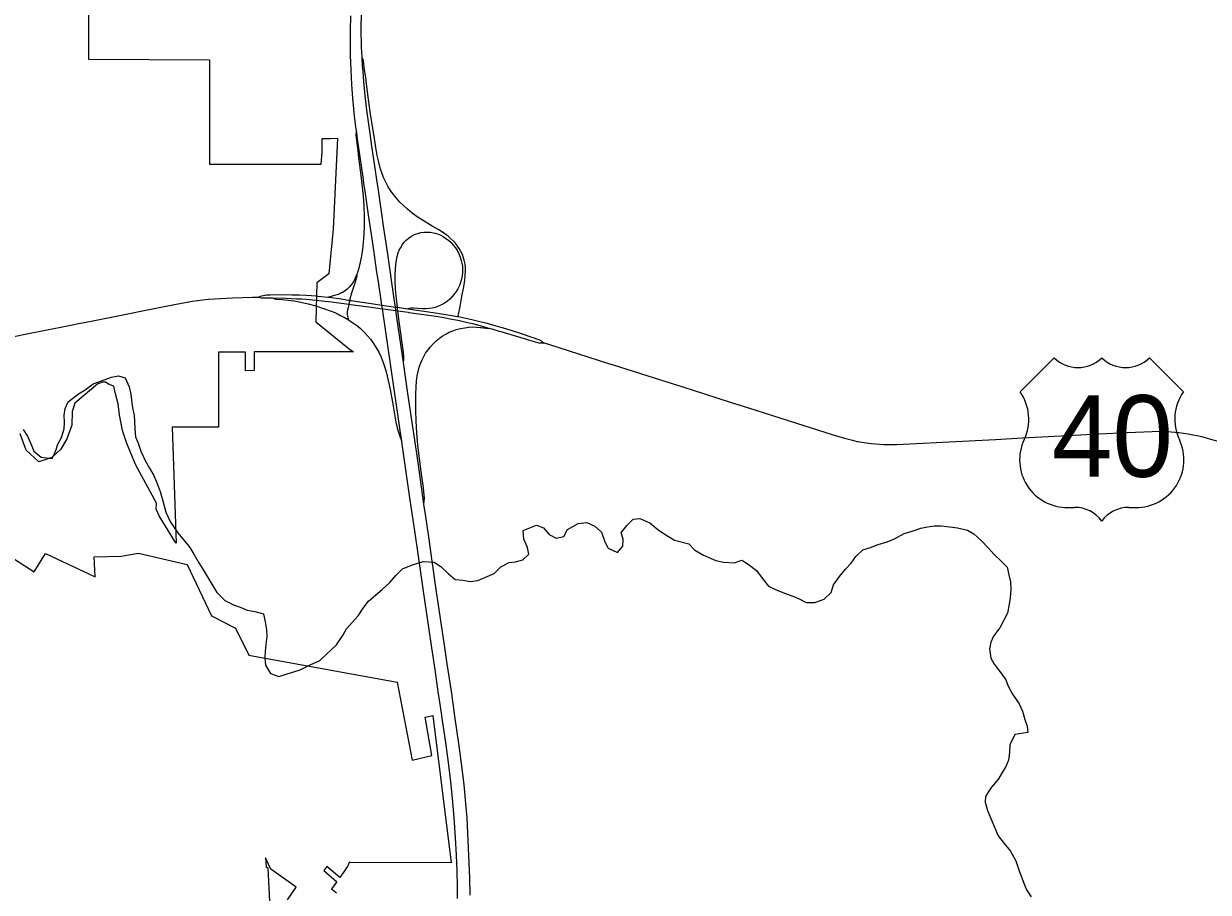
# Model space of a CAD drawing. Extents: x -29.6 to 34, y 0 to 22.
# Drawn here: x 4.78 to 7.023, y 15.149 to 16.793 of the extents above; entities that cross this region are included whole.
import ezdxf

# ---------------------------------------------------------------- set-up
doc = ezdxf.new("R2010")
doc.units = 0
for name, color, linetype in [('GM_X_Corporation', 7, 'Continuous'), ('GM_X_Interchange_Ramps', 7, 'Continuous'), ('GM_X_Interstate_Route', 7, 'Continuous'), ('GM_X_Minor_River', 7, 'Continuous'), ('GM_X_US_Route', 7, 'Continuous'), ('GM_X_US_Shield', 7, 'Continuous')]:
    doc.layers.add(name, color=color, linetype=linetype)

msp = doc.modelspace()

# ---------------------------------------------------------------- linework, layer by layer
at = {"layer": 'GM_X_Corporation'}
for points in [[(4.9028, 16.8101), (4.9028, 16.7263), (5.132, 16.7248), (5.132, 16.5273), (5.3437, 16.5274), (5.345, 16.5498), (5.3452, 16.5763), (5.3605, 16.5761), (5.3741, 16.5767), (5.3661, 16.4042), (5.3581, 16.3201), (5.3349, 16.3026), (5.3331, 16.2292), (5.3961, 16.178), (5.4045, 16.1724), (5.3388, 16.1724), (5.2167, 16.1724), (5.2167, 16.1371), (5.2001, 16.1361), (5.2001, 16.1716), (5.149, 16.1716), (5.149, 16.0297), (5.061, 16.0296), (5.0687, 15.8101), (5.0658, 15.8145), (5.0369, 15.8619), (5.0312, 15.874), (5.0318, 15.8857), (4.9919, 15.9586), (4.9821, 15.9835), (4.9751, 16.0008), (4.967, 16.0233), (4.9618, 16.0528), (4.959, 16.0736), (4.9543, 16.0926), (4.9509, 16.1071), (4.9422, 16.1106), (4.9353, 16.1146), (4.9295, 16.1146), (4.9203, 16.1117), (4.8771, 16.0751), (4.8717, 16.0591), (4.8711, 16.0331), (4.862, 16.0072), (4.8508, 15.9878), (4.8336, 15.9721), (4.809, 15.9638), (4.7852, 15.9862), (4.7733, 16.0172)], [(4.7451, 15.7911), (4.8002, 15.7559), (4.8217, 15.7904), (4.9154, 15.7459), (4.9137, 15.7841), (4.9645, 15.7851), (4.9978, 15.791), (5.0895, 15.7694), (5.1357, 15.6726), (5.1812, 15.649), (5.2066, 15.5978), (5.4873, 15.5465), (5.5157, 15.399), (5.5531, 15.4077), (5.5404, 15.4802), (5.5545, 15.4835), (5.5896, 15.2044), (5.3981, 15.2052), (5.3971, 15.2062), (5.3954, 15.2018), (5.3946, 15.2), (5.3936, 15.1982), (5.3929, 15.197), (5.3866, 15.1876), (5.3786, 15.1767), (5.354, 15.1979), (5.3487, 15.1899), (5.3729, 15.1688), (5.3632, 15.1551), (5.3722, 15.1481)], [(5.2797, 15.1344), (5.2959, 15.1588), (5.2482, 15.1927), (5.2382, 15.2139), (5.239, 15.1973), (5.2424, 15.1949), (5.2462, 15.1189)]]:
    msp.add_lwpolyline(points, dxfattribs=at)
at = {"layer": 'GM_X_Interchange_Ramps'}
for points in [[(5.6026, 16.2391), (5.6033, 16.2426), (5.6063, 16.2581), (5.6099, 16.2769), (5.6135, 16.2955), (5.6154, 16.3077), (5.6162, 16.3165), (5.6167, 16.3251), (5.6164, 16.3324), (5.6157, 16.3382), (5.6142, 16.346), (5.613, 16.3502), (5.6107, 16.3564), (5.608, 16.3623), (5.6048, 16.3681), (5.6024, 16.3717), (5.5975, 16.378), (5.5941, 16.3818), (5.5872, 16.3883), (5.5838, 16.3911), (5.5749, 16.3974), (5.5663, 16.4029), (5.5537, 16.4103), (5.5351, 16.4216), (5.5271, 16.4268), (5.5159, 16.4349), (5.5068, 16.4421), (5.4992, 16.449), (5.4925, 16.4556), (5.4857, 16.4632), (5.4799, 16.4707), (5.4748, 16.4778), (5.4699, 16.4859), (5.4657, 16.4936), (5.4617, 16.5021), (5.4575, 16.513), (5.4559, 16.5178), (5.4523, 16.5312), (5.4497, 16.544), (5.447, 16.5591), (5.4444, 16.5764), (5.4371, 16.6224), (5.433, 16.6498), (5.4293, 16.6794), (5.4277, 16.6913), (5.4256, 16.7063), (5.4243, 16.7175), (5.4237, 16.7222), (5.4234, 16.7238), (5.4231, 16.7249), (5.4227, 16.7259), (5.4224, 16.7267), (5.4217, 16.7284), (5.4209, 16.7297)], [(5.4103, 16.5908), (5.4098, 16.5886), (5.4094, 16.5865), (5.4092, 16.585), (5.4092, 16.5824), (5.4134, 16.5472), (5.4135, 16.5454), (5.4192, 16.5011), (5.4212, 16.4837), (5.4228, 16.4671), (5.424, 16.4482), (5.4247, 16.4278), (5.4247, 16.4104), (5.4242, 16.3944), (5.423, 16.3791), (5.4216, 16.3668), (5.4198, 16.3539), (5.4175, 16.3417), (5.4148, 16.3304), (5.4117, 16.3207), (5.4111, 16.319), (5.4093, 16.3146), (5.4065, 16.3086), (5.404, 16.3043), (5.4002, 16.2989), (5.3969, 16.2951), (5.3927, 16.2911), (5.3886, 16.2879), (5.3837, 16.2848), (5.3818, 16.2837), (5.38, 16.2829), (5.3778, 16.2818), (5.3754, 16.2809), (5.3731, 16.2801), (5.3601, 16.2763), (5.3577, 16.2756)], [(5.499, 16.152), (5.4998, 16.1569), (5.5001, 16.16), (5.5001, 16.1627), (5.4994, 16.1715), (5.4905, 16.2343), (5.4884, 16.2498), (5.4881, 16.2523), (5.4876, 16.2565), (5.4859, 16.2726), (5.4843, 16.2914), (5.4836, 16.3067), (5.4835, 16.3184), (5.4838, 16.3278), (5.4845, 16.3373), (5.4857, 16.346), (5.4871, 16.3524), (5.4891, 16.3593), (5.4913, 16.3648), (5.4939, 16.37), (5.4974, 16.3755), (5.5006, 16.3795), (5.5046, 16.3837), (5.5079, 16.3866), (5.5126, 16.39), (5.5164, 16.3922), (5.5216, 16.3947), (5.5264, 16.3963), (5.5321, 16.3978), (5.5379, 16.3986), (5.543, 16.3989), (5.5488, 16.3987), (5.5531, 16.3981), (5.5595, 16.3967), (5.5637, 16.3954), (5.5697, 16.3928), (5.5742, 16.3905), (5.5797, 16.3869), (5.5843, 16.3833), (5.5892, 16.3789), (5.5936, 16.3741), (5.5976, 16.3689), (5.6012, 16.3634), (5.6042, 16.3575), (5.6067, 16.3515), (5.6087, 16.3452), (5.6098, 16.3403), (5.6107, 16.3338), (5.611, 16.3287), (5.6109, 16.3221), (5.6103, 16.3163), (5.6091, 16.3099), (5.6073, 16.3036), (5.605, 16.2975), (5.6021, 16.2916), (5.5992, 16.2865), (5.5954, 16.2812), (5.5916, 16.2767), (5.587, 16.2721), (5.5825, 16.2684), (5.5771, 16.2646), (5.5714, 16.2614), (5.5655, 16.2586), (5.5593, 16.2564), (5.5537, 16.2549), (5.5479, 16.2539), (5.5414, 16.2534), (5.5356, 16.2534), (5.5179, 16.2546), (5.5136, 16.2546), (5.5101, 16.2543), (5.5075, 16.2536)], [(5.4111, 16.319), (5.4106, 16.3161), (5.41, 16.3127), (5.4086, 16.3072), (5.4083, 16.3058), (5.4044, 16.2943), (5.3993, 16.2793), (5.3987, 16.2765), (5.3979, 16.2724), (5.3974, 16.27), (5.3966, 16.2658), (5.3958, 16.2624)], [(5.2514, 16.2744), (5.2527, 16.2737), (5.2548, 16.2726), (5.2566, 16.2722), (5.2585, 16.2719), (5.2704, 16.2713), (5.2757, 16.2709), (5.2811, 16.2702), (5.2865, 16.2696), (5.292, 16.2688), (5.3049, 16.2664), (5.319, 16.2631), (5.3332, 16.259)], [(5.3958, 16.2624), (5.3943, 16.2554), (5.3934, 16.2517), (5.3926, 16.2488), (5.3923, 16.2459), (5.3925, 16.2429), (5.3931, 16.2404), (5.3941, 16.237), (5.3954, 16.2326)], [(5.3332, 16.259), (5.3481, 16.2542), (5.3623, 16.2491), (5.3692, 16.2464), (5.3756, 16.2434), (5.3785, 16.2419), (5.3876, 16.2372), (5.3954, 16.2326), (5.397, 16.2317), (5.4055, 16.2261), (5.4125, 16.2208), (5.418, 16.2162), (5.4249, 16.2096), (5.4313, 16.2027), (5.4368, 16.1959), (5.4423, 16.1882), (5.4478, 16.1796), (5.4524, 16.1714), (5.4569, 16.1622), (5.461, 16.1521), (5.4642, 16.1424), (5.4666, 16.134), (5.4705, 16.1177), (5.474, 16.1006), (5.4784, 16.077), (5.4847, 16.0393), (5.4874, 16.028), (5.4896, 16.0201), (5.4917, 16.0142), (5.4961, 16.0015)], [(5.538, 15.884), (5.5384, 15.8891), (5.5389, 15.8948), (5.5387, 15.9008), (5.5371, 15.9146), (5.5328, 15.9456), (5.5289, 15.9745), (5.5265, 15.9962), (5.5246, 16.0179), (5.5232, 16.0412), (5.5225, 16.0616), (5.5224, 16.0783), (5.5226, 16.0921), (5.5231, 16.106), (5.524, 16.1169), (5.5254, 16.127), (5.527, 16.1348), (5.5291, 16.1433), (5.5321, 16.1515), (5.5343, 16.1569), (5.5382, 16.1647), (5.5412, 16.1696), (5.5458, 16.1762), (5.5504, 16.1819), (5.5558, 16.1878), (5.5611, 16.1928), (5.5673, 16.1978), (5.5726, 16.2016), (5.5795, 16.2058), (5.586, 16.2091), (5.5927, 16.2119), (5.5996, 16.2142), (5.6073, 16.2163), (5.6152, 16.2179), (5.6231, 16.2189), (5.6304, 16.2192), (5.6377, 16.2191), (5.6442, 16.2185), (5.6466, 16.2181), (5.655, 16.2171), (5.6588, 16.2168), (5.6629, 16.2166)]]:
    msp.add_lwpolyline(points, dxfattribs=at)
at = {"layer": 'GM_X_Interstate_Route'}
for points in [[(5.6016, 15.1368), (5.6014, 15.1594), (5.6007, 15.1893), (5.5995, 15.2191), (5.5978, 15.2519), (5.5953, 15.2904), (5.5921, 15.3267), (5.5888, 15.3585), (5.5844, 15.3947), (5.5793, 15.4322), (5.573, 15.474), (5.5703, 15.4923), (5.5666, 15.5168), (5.5656, 15.5237), (5.5589, 15.5705), (5.553, 15.6116), (5.5368, 15.7233), (5.5276, 15.7852), (5.5205, 15.8335), (5.5121, 15.8911), (5.4961, 16.0015), (5.46, 16.249), (5.4594, 16.2537), (5.4584, 16.2607), (5.4558, 16.279), (5.454, 16.2912), (5.4524, 16.3003), (5.4484, 16.3275), (5.4438, 16.3603), (5.4398, 16.3859), (5.4339, 16.4272), (5.4265, 16.4762), (5.4244, 16.4908), (5.4229, 16.503), (5.4156, 16.5541), (5.413, 16.571), (5.4103, 16.5908), (5.4091, 16.5985), (5.4077, 16.608), (5.4065, 16.619), (5.4035, 16.6527), (5.4016, 16.6781), (5.4001, 16.7064), (5.3992, 16.7333), (5.3989, 16.7588), (5.399, 16.7806), (5.3998, 16.8082)], [(5.4854, 16.2469), (5.485, 16.2502), (5.484, 16.257), (5.4819, 16.2722), (5.479, 16.2903), (5.4765, 16.3077), (5.4739, 16.326), (5.4712, 16.3439), (5.4687, 16.3614), (5.4621, 16.4062), (5.4582, 16.4332), (5.4545, 16.4601), (5.4519, 16.478), (5.4486, 16.4981), (5.4464, 16.5153), (5.4395, 16.5618), (5.4359, 16.5856), (5.43, 16.6296), (5.4284, 16.6409), (5.4268, 16.6566), (5.424, 16.6847), (5.4233, 16.6926), (5.4226, 16.7036), (5.4219, 16.7132), (5.4209, 16.7297), (5.4209, 16.7306), (5.4198, 16.7482), (5.4193, 16.7851), (5.4195, 16.8135)], [(5.553, 15.7803), (5.5476, 15.8174), (5.5413, 15.8606), (5.538, 15.884), (5.5301, 15.9399), (5.5236, 15.9839), (5.5073, 16.0933), (5.499, 16.152), (5.4869, 16.237), (5.4854, 16.2469)], [(5.6252, 15.1435), (5.6247, 15.1755), (5.6204, 15.2752), (5.6197, 15.2897), (5.618, 15.31), (5.6138, 15.352), (5.6102, 15.3831), (5.6045, 15.4264), (5.5967, 15.4826), (5.5947, 15.4968), (5.5913, 15.5201), (5.5911, 15.5216), (5.5821, 15.5812), (5.5769, 15.6165), (5.5613, 15.7224), (5.5537, 15.7757), (5.553, 15.7803)]]:
    msp.add_lwpolyline(points, dxfattribs=at)
at = {"layer": 'GM_X_Minor_River'}
for points in [[(4.9118, 16.1114), (4.9277, 16.1172), (4.9462, 16.124), (4.9595, 16.1264), (4.9724, 16.1229), (4.98, 16.1056), (4.9828, 16.0923), (4.9846, 16.0804), (4.9865, 16.0662), (4.9893, 16.052), (4.9902, 16.04), (4.9908, 16.0258), (4.9922, 16.0111), (4.9967, 15.9992), (5.0017, 15.9841), (5.0102, 15.9664), (5.0183, 15.9518), (5.0263, 15.9377), (5.0331, 15.9231), (5.0385, 15.908), (5.0435, 15.8903), (5.0494, 15.8686), (5.0584, 15.8496), (5.0718, 15.8297), (5.0839, 15.8151), (5.0946, 15.8019), (5.1022, 15.7891), (5.112, 15.7727), (5.1214, 15.7577), (5.1291, 15.7448), (5.1362, 15.7325), (5.1461, 15.7166), (5.1608, 15.7011), (5.1772, 15.6928), (5.1901, 15.6889), (5.2034, 15.6828), (5.2181, 15.6802), (5.234, 15.6759), (5.2382, 15.6577), (5.24, 15.6458), (5.2405, 15.6329), (5.2389, 15.6182), (5.2376, 15.6053), (5.2368, 15.5925), (5.2378, 15.5791), (5.2477, 15.5632), (5.2632, 15.5571), (5.2773, 15.5621), (5.3034, 15.5703), (5.3228, 15.5793), (5.3409, 15.5875), (5.3537, 15.5995), (5.3726, 15.6174), (5.3853, 15.6366), (5.3915, 15.6478), (5.402, 15.6594), (5.4135, 15.6724), (5.4227, 15.6871), (5.4328, 15.7), (5.446, 15.7112), (5.4587, 15.7224), (5.4733, 15.7354), (5.4847, 15.7488), (5.4974, 15.7614), (5.5142, 15.7681), (5.5363, 15.775), (5.5576, 15.7738), (5.5701, 15.7655), (5.5839, 15.7522), (5.5968, 15.7412), (5.6123, 15.7396), (5.6252, 15.7374), (5.6402, 15.7393), (5.6707, 15.7524), (5.6834, 15.765), (5.6993, 15.7731), (5.7113, 15.7745), (5.725, 15.7786), (5.7364, 15.7889), (5.7341, 15.8018), (5.7269, 15.8177), (5.7259, 15.8341), (5.7511, 15.8441), (5.7644, 15.8388), (5.7752, 15.8265), (5.7885, 15.8195), (5.8026, 15.8222), (5.8096, 15.8356), (5.8299, 15.8469), (5.8463, 15.8492), (5.8614, 15.8418), (5.8739, 15.8308), (5.8802, 15.8122), (5.8869, 15.8007), (5.9043, 15.7924), (5.9148, 15.8044), (5.9152, 15.8173), (5.9111, 15.8293), (5.9221, 15.8435), (5.934, 15.8552), (5.9468, 15.8566)], [(4.7795, 16.0251), (4.7876, 16.0123), (4.7943, 15.9968), (4.7997, 15.984), (4.8135, 15.9725), (4.8343, 15.9705), (4.8409, 15.9852), (4.8448, 15.9972), (4.8518, 16.0101), (4.8566, 16.0266), (4.8574, 16.0381), (4.8568, 16.0523), (4.8585, 16.0648), (4.8642, 16.0777), (4.884, 16.0925), (4.8964, 16.1001), (4.9118, 16.1114)], [(5.9468, 15.8566), (5.9655, 15.8483), (5.981, 15.836), (5.9926, 15.8276), (6.0126, 15.8154), (6.0392, 15.8084), (6.0504, 15.7974), (6.0669, 15.7873), (6.0908, 15.7773), (6.105, 15.7738), (6.1259, 15.7727), (6.14, 15.7777), (6.152, 15.7698), (6.1676, 15.7583), (6.1783, 15.7437), (6.1904, 15.7283), (6.2037, 15.7222), (6.2206, 15.7152), (6.2366, 15.7095), (6.2481, 15.7043), (6.2614, 15.6977), (6.2783, 15.6974), (6.2955, 15.7038), (6.3092, 15.7163), (6.3135, 15.731), (6.3249, 15.747), (6.3359, 15.7604), (6.3469, 15.7721), (6.3556, 15.7846), (6.3688, 15.7971), (6.3834, 15.8016), (6.398, 15.8075), (6.4148, 15.8121), (6.4285, 15.8179), (6.447, 15.8283), (6.4643, 15.8333), (6.4784, 15.8383), (6.4912, 15.841), (6.5045, 15.8429), (6.5174, 15.8426), (6.5338, 15.8405), (6.5479, 15.8388), (6.567, 15.8345), (6.579, 15.8275), (6.5928, 15.8151), (6.6067, 15.8006), (6.6169, 15.7891), (6.6312, 15.7754), (6.6423, 15.7644), (6.6451, 15.7498), (6.6483, 15.7365), (6.6488, 15.7227), (6.6476, 15.7063), (6.6455, 15.6907), (6.6425, 15.6774), (6.6281, 15.6493), (6.6162, 15.6337), (6.6114, 15.6226), (6.6088, 15.6101), (6.6112, 15.5924), (6.6174, 15.5809), (6.6304, 15.5645), (6.6393, 15.5513), (6.6443, 15.5393), (6.6519, 15.5238), (6.6649, 15.5057), (6.6712, 15.4916), (6.6757, 15.476), (6.6798, 15.4632), (6.6812, 15.4512), (6.6564, 15.4475), (6.6473, 15.4279), (6.6465, 15.4132), (6.6448, 15.399), (6.6396, 15.387), (6.6325, 15.3758), (6.6255, 15.3634), (6.6106, 15.3455), (6.6014, 15.3303), (6.6002, 15.3192), (6.6047, 15.3037), (6.6101, 15.2918), (6.6182, 15.2723), (6.6249, 15.2559), (6.6366, 15.2413), (6.6486, 15.2268), (6.6585, 15.2086), (6.6643, 15.1914), (6.6725, 15.1692), (6.6788, 15.1537), (6.6873, 15.1405)]]:
    msp.add_lwpolyline(points, dxfattribs=at)
at = {"layer": 'GM_X_US_Route'}
for points in [[(4.7331, 16.1955), (4.7585, 16.2006), (4.786, 16.2061), (4.8634, 16.2216), (4.8839, 16.2256), (4.8913, 16.2271), (4.9141, 16.2317), (4.9491, 16.2387), (4.9805, 16.2449), (4.9986, 16.2485), (5.049, 16.2587), (5.079, 16.2646), (5.0897, 16.2664), (5.1, 16.2682), (5.1093, 16.2695), (5.1102, 16.2696), (5.1192, 16.2709), (5.1294, 16.2718), (5.1413, 16.2728), (5.1753, 16.2745), (5.2133, 16.2755), (5.2248, 16.2759)], [(5.2248, 16.2759), (5.2288, 16.2775), (5.2337, 16.279), (5.2399, 16.28), (5.2471, 16.2804), (5.2623, 16.2806), (5.2877, 16.2801), (5.3019, 16.2799), (5.3141, 16.2794), (5.3251, 16.2787), (5.3335, 16.2781)], [(5.2248, 16.2759), (5.23, 16.2747), (5.2349, 16.2742), (5.2514, 16.2744), (5.2776, 16.2737), (5.2969, 16.2728), (5.298, 16.2728)], [(5.298, 16.2728), (5.3062, 16.2724), (5.3147, 16.2717), (5.3333, 16.2698)], [(5.3333, 16.2698), (5.3627, 16.2668), (5.3958, 16.2624)], [(5.3335, 16.2781), (5.3378, 16.2777), (5.356, 16.2758), (5.3577, 16.2756), (5.3777, 16.273), (5.3951, 16.2703)], [(5.3951, 16.2703), (5.3974, 16.27), (5.3994, 16.2696), (5.4422, 16.2631), (5.4584, 16.2607), (5.484, 16.257), (5.4876, 16.2565), (5.4956, 16.2553), (5.5075, 16.2536), (5.5554, 16.2466), (5.5835, 16.2425), (5.6015, 16.2393)], [(5.3958, 16.2624), (5.4038, 16.2613), (5.4385, 16.2566)], [(5.4385, 16.2566), (5.4594, 16.2537), (5.4608, 16.2536), (5.485, 16.2502), (5.4884, 16.2498), (5.508, 16.2471)], [(5.508, 16.2471), (5.5092, 16.2469), (5.561, 16.2394), (5.5754, 16.237), (5.5905, 16.2343), (5.602, 16.232)], [(5.6015, 16.2393), (5.6026, 16.2391), (5.6057, 16.2385), (5.6285, 16.2335), (5.644, 16.2298), (5.6575, 16.2264), (5.6631, 16.2248)], [(5.602, 16.232), (5.6054, 16.2313), (5.6177, 16.2286), (5.6302, 16.2255), (5.6437, 16.2221), (5.6629, 16.2166)], [(5.6629, 16.2166), (5.6665, 16.2157), (5.6805, 16.2116), (5.6836, 16.2107), (5.728, 16.1975), (5.7532, 16.1899), (5.7555, 16.1893), (5.7578, 16.189), (5.7601, 16.1889), (5.7654, 16.1891)], [(5.6631, 16.2248), (5.6813, 16.2197), (5.6858, 16.2183), (5.7042, 16.2125), (5.7218, 16.2067), (5.7565, 16.1947), (5.7592, 16.1934), (5.7614, 16.192), (5.7654, 16.1891)], [(5.7654, 16.1891), (5.7874, 16.182), (5.7954, 16.1795)], [(5.7954, 16.1795), (5.8305, 16.1684), (5.8873, 16.1502), (5.8941, 16.148), (5.9478, 16.1312), (6.0456, 16.1), (6.1178, 16.077), (6.1524, 16.0659), (6.2572, 16.0327), (6.3127, 16.0149), (6.3343, 16.0084), (6.3491, 16.0046), (6.358, 16.0026), (6.3596, 16.0024), (6.3669, 16.0012), (6.3761, 15.9997), (6.3848, 15.9986), (6.3926, 15.9977), (6.4007, 15.9971), (6.4078, 15.9967), (6.4152, 15.9966), (6.4326, 15.9968), (6.4828, 15.9992), (6.5322, 16.0019), (6.62, 16.0063), (6.6704, 16.0092), (6.7809, 16.0149), (6.8158, 16.0168), (6.8696, 16.0197), (6.9168, 16.0214), (6.9323, 16.0217), (6.9422, 16.0214), (6.9527, 16.0208), (6.9602, 16.0201), (6.9659, 16.0196)], [(6.9659, 16.0196), (6.968, 16.0194), (6.9762, 16.0183), (6.9846, 16.0169), (6.9939, 16.0151), (7.0018, 16.0135), (7.0099, 16.0117), (7.0188, 16.0092), (7.027, 16.0069), (7.0363, 16.004), (7.0441, 16.0015), (7.0529, 15.9983), (7.0601, 15.9955), (7.0671, 15.9925), (7.0836, 15.9848), (7.0923, 15.9806), (7.1005, 15.9761), (7.1088, 15.9714), (7.1192, 15.9651)]]:
    msp.add_lwpolyline(points, dxfattribs=at)
at = {"layer": 'GM_X_US_Shield'}
for p, q in [((6.7311, 16.1608), (6.6667, 16.0964)), ((6.9757, 16.0964), (6.9113, 16.1608)), ((6.7568, 15.8775), (6.7697, 15.8775)), ((6.8727, 15.8775), (6.8856, 15.8775))]:
    msp.add_line(p, q, dxfattribs=at)
for centre, radius, start, end in [((6.7762, 16.2067), 0.0644, 225.573, 314.427), ((6.8663, 16.2067), 0.0644, 225.573, 314.427), ((6.5929, 16.0447), 0.0901, 334.5471, 35.0009), ((7.0495, 16.0447), 0.0901, 144.9991, 205.4529), ((6.7558, 15.9676), 0.0901, 154.8319, 270.6383), ((6.8866, 15.9676), 0.0901, 269.3617, 25.1681), ((6.7697, 15.8132), 0.0644, 36.8699, 90), ((6.8727, 15.8132), 0.0644, 90, 143.1301)]:
    msp.add_arc(centre, radius, start, end, dxfattribs=at)

# ---------------------------------------------------------------- texts
msp.add_text('40', height=0.1545, dxfattribs=at).set_placement((6.7264, 15.9355))

doc.saveas('drawing.dxf')
